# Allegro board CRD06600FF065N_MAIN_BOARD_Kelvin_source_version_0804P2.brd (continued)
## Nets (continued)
N165538091: RV1.1 RV2.2
N165801940: D1.1(A) R4.1

Pads without a net: CON2 2; J3 1 6 8 13; J4 5 9 12; J7 3 4 7 8; J8 3; NOREF#2 1; NOREF#7 1; NOREF#9 1; NOREF#14 1; NOREF#15 1; NOREF#16 1; T1 1 4 8 10 11; U5 7 12 13; U10 6 7 10 11; U35 1 4

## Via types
v1: diameter 0.61, hole 0.305, TOP to BOTTOM, 516 vias

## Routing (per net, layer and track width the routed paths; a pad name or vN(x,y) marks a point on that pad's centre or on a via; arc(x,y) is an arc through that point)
+5V_A: length 118
  TOP w0.508: R596.1 107.39,137.04 v1(107.6,136.83)
  TOP w0.635: C610.2 108.05,137.28 v1(107.6,136.83)
  ART05 w0.508: v1(85.34,140.34) 87.89,137.79 103.53,137.79 105.49,135.84 106.61,135.84 v1(107.6,136.83) 104.78,139.65 v1(104.78,142.24) 104.78,143.72 121.83,160.77 132.39,160.77 134.39,162.78 134.39,171.54 138.99,176.13 154.7,176.13 v1(156.21,174.62)
  BOTTOM w0.508: v1(107.6,136.83) 107.34,136.83 107.01,137.16 R242.2 ; v1(104.78,142.24) 104.65,142.12 C611.1 R246.1 ; R573.1 159.26,169.54 C596.2 157.6,170.06 156.21,171.45 v1(156.21,174.62)
-3V_PSW1: length 207.2
  ART05 w0.508: v1(205.74,71.75) 205.74,100.61 191.92,114.43 164.85,114.43 162.94,116.33 124.49,116.33 v1(119.28,121.54) 119.28,121.06 114.55,116.33 v1(99.95,116.33) 84.33,116.33 77.98,122.68 v1(76.58,122.68)
  BOTTOM w0.508: U106.8 v1(119.28,121.54) 119.28,122.49 C46.2 119.01,122.94 C614.2 ; v1(99.95,116.33) 99.95,111.9 ZD14.1 102.1,110.74 103,110.74 C45.2 ; C525.2 63.78,118.62 64.26,119.1 64.88,119.1 D47.1 65.16,117.94 66.76,116.34 C37.2 70.37,116.34 ZD13.1 75.74,117.09 76.2,117.55 U5.9 76.2,120.02 76.58,120.39 C38.2 76.58,121.29 v1(76.58,122.68)
-3V_PSW2: length 60.9
  ART03 w0.508: v1(162.2,121.54) 164.24,119.51 177.16,119.51 193.43,103.24 193.43,99.6 191.18,97.36 191.18,90.12 v1(192.41,88.9)
  BOTTOM w0.508: C499.2 C613.2 161.94,122.94 C41.2 162.2,122.49 v1(162.2,121.54) U104.8
-3V_PSW3: length 44.4
  ART05 w0.508: v1(87,117.47) 83.94,120.53 82.28,120.53 82.19,120.45 81.51,120.45 80.34,121.61 80.34,122.86 v1(80.13,123.07) 80.26,123.19 80.26,128.02 73.66,134.62 v1(63.5,134.62)
  BOTTOM w0.508: v1(80.13,123.07) C496.2 81.28,121.54 C33.2 81.02,120.31 81.52,119.82 82.16,119.82 82.55,119.42 U5.14 ; v1(87,117.47) C524.2 87.12,118.75 D48.1
-3V_PSW4: length 89.8
  ART03 w0.508: v1(124.97,41.66) 125.15,41.47 135.89,41.47 139.01,38.35 155.45,38.35 158.75,41.66 v1(165.82,41.66)
  ART05 w0.508: U21.5 170.31,24.13 170.81,24.64 170.81,36.66 v1(165.82,41.66)
  BOTTOM w0.508: C561.2 165.82,42.8 C563.2 165.95,41.78 v1(165.82,41.66) 171.41,41.66 173.37,43.62 U109.8 ; C547.2 124.93,42.8 C549.2 125.06,41.75 v1(124.97,41.66) 130.52,41.66 132.49,43.62 U107.8 ; U21.5 169.17,24.13
-3V_PSW5: length 42.4
  ART05 w0.508: U19.5 122.43,26.04 117.86,30.61 117.86,37.34 115.95,39.24 110.87,39.24 v1(108.2,41.91)
  BOTTOM w0.508: C542.2 107.82,41.91 v1(108.2,41.91) C537.2 109.09,42.93 109.47,42.55 112.52,42.55 113.92,43.94 U108.8
-3V_PSW7: length 29.7
  ART05 w0.508: v1(149.05,41.91) 147.45,40.31 147.45,34.8 151,31.24 151,28.01 U20.5
  BOTTOM w0.508: U110.8 154.76,43.94 153.37,42.55 150.62,42.55 150.24,42.93 C552.2 v1(149.05,41.91) 148.67,41.91 C556.2
-3V_PSW9: length 97.7
  ART02 w0.508: U22.5 82.74,16.13 55.45,16.13 52.44,19.14 25.8,19.14 20.96,23.98 20.96,40.13 v1(22.86,42.04)
  BOTTOM w0.508: C570.2 22.61,42.04 v1(22.86,42.04) C566.2 23.87,42.93 24.26,42.55 27.18,42.55 28.57,43.94 U112.8
-3V_PSW10: length 121.1
  ART05 w0.508: U24.5 112.56,16.23 112.56,20.01 110.78,21.8 108.02,21.8 99.95,29.87 99.95,36.58 94.49,42.04 v1(83.07,42.04) 80.15,44.96 77.47,44.96 72.77,40.26 64.39,40.26 63.12,38.99 57.02,38.99 53.98,42.04 v1(42.16,42.04)
  BOTTOM w0.508: v1(83.07,42.04) 88.65,42.04 90.62,44 U113.8 ; v1(83.07,42.04) 82.43,42.04 C589.2 ; v1(83.07,42.04) 83.19,42.16 C591.2 ; C575.2 41.53,42.04 v1(42.16,42.04) ; v1(42.16,42.04) 47.75,42.04 49.72,44 U111.8 ; v1(42.16,42.04) 42.29,42.16 C577.2
-3V_PSW11: length 88.7
  ART02 w0.508: U23.5 96.22,14.71 96.22,20.24 95.12,21.34 95.12,49.91 91.02,54.02 74.71,54.02 73.74,53.05 73.74,47.58 68.71,42.55 64.26,42.55 v1(63.75,42.04)
  BOTTOM w0.508: U114.8 69.47,43.94 68.07,42.55 65.15,42.55 64.77,42.93 C580.2 v1(63.75,42.04) 63.5,42.04 C584.2
AGND: length 572.5
  TOP w0.381: U10.8 v1(101.35,38.1)
  TOP w0.508: C101.2 107.68,27.82 107.65,27.85 C102.1 v1(105.96,26.86)
  ART02 w0.508: J5.6 218.43,42.55 ; J5.8 218.43,40.01 ; 159.45,7.62 J7.9 161.35,9.51 ; J3.3 218.43,71.75 ; J3.21 218.43,94.61 ; 166.43,3.19 J7.6 ; 212.1,71.75 214,71.75 ; 212.1,69.22 214,69.22 214,67.32
  ART02 w1.016: 205.23,16.36 C594.2 ; C594.2 208.79,16.36 ; C594.2 207.01,18.13 ; C594.2 207.01,14.58 ; U20.2 150.29,17.78 ; U20.2 148.39,19.67 ; U20.2 146.5,17.78 ; U21.2 169.48,18.4 ; U21.2 167.58,16.51 ; U21.2 171.37,16.51 ; U19.2 132,18.41 ; U19.2 128.21,18.41 ; U19.2 130.11,20.31
  ART03 w1.016: U15.2 201.73,65.27 ; U15.2 200.6,64.14 ; U15.2 202.87,64.14 ; U17.2 201.73,86.22 ; U17.2 200.6,85.09 ; U17.2 202.87,85.09 ; J3.21 217.67,94.61
  GND04 w0.508: 166.43,3.19 J7.6 ; J7.9 161.35,9.51
  GND04 w1.016: U19.2 132,18.41 ; U19.2 130.11,20.31 ; U19.2 128.21,18.41 ; 205.23,16.36 C594.2 207.01,18.13 ; 148.39,18.41 148.39,20.31 ; 148.39,18.41 150.29,18.41 ; 148.39,18.41 146.5,18.41 ; U21.2 169.48,18.4 ; U21.2 167.58,16.51 ; U21.2 171.37,16.51
  ART05 w0.254: 216.79,40.01 218.97,37.82 218.97,31.55 v1(217.34,29.92)
  ART05 w0.508: 214,69.22 J3.3 ; v1(218.43,51.29) 218.67,51.04 218.67,41.03 217.64,40.01 J5.8 ; v1(211.89,38.94) 210.82,37.87 v1(210.82,33.02) 209.65,31.85 209.65,29.71 200.21,20.26 v1(189.87,20.26) 181.67,20.26 v1(181.61,20.32) 177.42,16.13 v1(175.9,16.13) 169.86,16.13 U21.2 166.03,16.51 164.01,14.49 151.69,14.49 U20.2 147.32,17.78 144.03,14.49 128.18,14.49 125.47,17.2 125.47,19.41 111.51,33.37 111.51,33.85 111.02,34.34 v1(109.62,34.34) 108.21,34.34 106.54,32.66 106.54,27.45 v1(105.96,26.86) 109.27,26.86 113.95,22.18 113.95,18.7 122.48,10.17 200.83,10.17 C594.2 207.01,19.68 v1(207.65,20.32) 214.25,26.92 215.73,26.92 217.34,28.54 v1(217.34,29.92) ; 199.38,70.5 205.86,70.5 207.89,72.53 207.89,76.83 v1(212.09,81.03) ; U15.2 201.73,65.27 ; U15.2 202.87,64.14 ; U15.2 200.6,64.14
  ART05 w1.016: U18.2 59.69,143.69 ; U18.2 59.69,139.91 ; U18.2 61.58,141.8
  BOTTOM w0.381: C40.2 75.56,108.46 C598.2 ; C540.2 C541.2 v1(125.86,33.66) ; U103.5 v1(177.16,174.62) ; 115.57,109.48 115.57,109.47 ; C605.2 v1(113.92,32.64)
  BOTTOM w0.508: 159.66,115.44 159.92,115.7 163.95,115.7 C530.2 164.98,115.06 165.99,114.05 C531.2 166.75,113.66 167,113.41 C601.2 ; 159.66,115.44 159.66,115.73 158.88,115.73 158.39,115.24 U104.4 158.39,113.45 v1(157.66,112.72) 158.5,111.88 C43.2 ; 159.66,115.44 U104.3 ; R550.2 C544.2 v1(109.62,34.34) ; v1(189.17,47.55) 189.17,46.39 C604.1 ; C533.2 C532.2 v1(116.52,37.6) ; U106.3 116.74,115.7 ; 116.74,115.7 121.41,115.7 C48.2 122.81,115.06 123.32,114.55 C47.2 124.85,113.66 C602.2 ; 116.74,115.7 116.74,115.73 115.96,115.73 115.47,115.24 U106.4 115.47,113.45 v1(114.74,112.72) 115.57,111.88 C44.2 R73.2 ; C595.1 v1(174.62,177.16) ; R70.2 v1(78.11,107.31) ; C555.2 C554.2 174.91,36.14 v1(177.2,36.14) 177.2,35.96 177.98,35.18 C608.2 ; C88.2 v1(192.91,24.77) ; 123.19,139.7 121.92,138.43 C612.2 ; 123.19,139.7 120.02,142.88 U35.5 ; 123.19,139.7 124.46,139.7 125.96,138.2 134.72,138.2 137.41,140.89 137.41,143.89 138.96,145.44 142.29,145.44 144.76,147.91 144.76,152.23 145.36,152.83 145.36,155.9 144.93,156.33 C1.2 v1(144.15,164.47) ; v1(80.84,111.12) 81.28,111.57 U5.4 ; v1(204.4,43.33) 205.36,43.33 U9.3 ; R73.2 v1(114.68,110.49) ; R73.2 115.57,109.48 ; U4.4 v1(198.75,39.37) ; v1(158.5,109.48) R72.2 ; C27.1 180.09,170.81 180.72,171.45 v1(180.97,171.45) ; U107.3 v1(129.95,38.1) ; R554.2 v1(150.04,34.67) ; C607.2 v1(159.13,38.35) ; v1(121.82,33.66) C543.2 R548.2 ; U110.3 v1(152.22,40.51) ; U109.3 v1(170.83,40.51) ; C40.2 v1(75.56,107.31) ; C39.2 v1(76.83,107.31) ; v1(201.93,43.81) 202.05,43.94 R136.1 ; v1(195.07,46.15) 195.07,45.15 C84.1 ; C606.2 v1(126.35,31.12) ; R552.2 C557.2 v1(168.3,34.2) ; U107.4 v1(128.68,38.08) ; v1(157.73,38.73) C551.2 C550.2 ; C26.1 v1(181.71,177.16) ; C93.2 v1(201.67,39.25) ; U108.3 v1(111.38,38.17) ; U55.3 201.93,172.6 v1(200.66,171.33) R539.1 ; v1(182.37,27.69) 182.37,27.69 C603.1 ; C558.2 v1(151.55,34.67) ; C248.1 v1(190.14,29.72) ; U110.4 v1(150.95,40.51) ; R68.2 v1(80.64,107.31) ; U2.4 v1(193.55,172.72) 193.8,172.46 C592.2 196.08,171.33 C478.2 ; C597.1 v1(177.16,168.28) ; C35.2 v1(85.72,107.31) ; C36.2 v1(81.92,107.31) ; R69.2 v1(79.38,107.31) ; U109.4 v1(169.56,40.51) ; U108.4 v1(110.11,38.16) ; R67.2 v1(87,107.31)
  vias: v1(97.28,109.86) v1(115.95,104.78) v1(123.43,100.24) v1(130.18,100.24) v1(130.94,166.75) v1(130.94,165.61) v1(164.96,109.59) v1(167.78,109.36) v1(171.99,108.19) v1(180.21,99.95) v1(180.21,89.66) v1(182.88,16.89) v1(184.15,16.89) v1(185.42,16.89) v1(186.12,20.23) v1(186.69,16.89) v1(187.96,16.89) v1(189.23,16.89) v1(189.23,15.37) v1(190.5,15.37) v1(190.58,16.74) v1(191.85,16.74) v1(191.9,15.37) v1(193.12,16.74) v1(193.17,15.37) v1(194.39,16.74) v1(194.44,15.37) v1(194.82,86.49) v1(194.82,85.09) v1(195.58,66.1) v1(195.66,16.74) v1(195.71,15.37) v1(196.22,86.49) v1(197.1,16.76) v1(197.1,15.37) v1(197.61,86.49) v1(197.61,85.09) v1(198.12,17.72) v1(198.37,16.76) v1(199.64,16.76) v1(200.91,16.76) v1(201.93,18.36) v1(202.44,16.76) v1(203.2,65.41) v1(204.47,65.41) v1(212.58,51.29)
AGND_N: length 153.7
  TOP w0.508: C610.1 108.08,135.77 107.57,135.26 v1(107.57,135.25) ; C278.1 R243.2 v1(93.34,134.62) ; U34.4 v1(97.28,134.62) ; C281.2 v1(93.34,139.7)
  ART03 w1.016: 82.62,128.63 Q4.3 ; Q4.3 85.16,126.09 ; Q4.3 85.16,131.17 ; 69.85,139.91 U18.6 69.85,143.69 ; 35.77,126.5 D2.3 ; D2.3 38.15,128.89 ; D2.3 35.77,131.28
  GND04 w0.508: v1(163.19,174.62) 161.93,173.35 159.38,173.35 v1(158.12,174.62)
  ART05 w0.508: v1(158.12,174.62) 155.58,177.16 138.21,177.16 133.61,172.56 133.61,163.31 131.99,161.69 120.78,161.69 98.79,139.7 v1(93.34,139.7)
  BOTTOM w0.381: U103.4 v1(163.19,174.62) 163.19,173.74 163.58,173.35 U103.3
  BOTTOM w0.508: C496.1 C497.2 82.55,125.73 ; v1(101.6,136.81) 101.6,136.81 Q60.3 ; v1(158.12,174.62) 158.75,173.99 C596.1 159.38,171.57 159.89,172.09 C30.2 C29.1 ; v1(93.34,139.7) 88.87,139.7 88.27,139.09 88.27,136.4 ; C611.2 106.17,142.27 105.22,143.22 104.49,143.22 103.5,142.24 v1(103.5,140.97) C282.1 ; v1(107.57,135.25) 106.93,134.62 C280.2 R241.1 ; C524.1 87,121.16 C599.1 ; v1(107.57,138.43) C279.2
  vias: v1(80.9,138.94) v1(80.9,136.91) v1(83.19,134.62) v1(83.18,133.63) v1(84.44,133.65) v1(84.45,134.62) v1(85.34,136.78) v1(85.72,134.62) v1(85.74,133.65) v1(87,134.62) v1(87,133.69) v1(88.27,134.62) v1(88.33,133.74) v1(89.53,134.62) v1(89.56,133.73) v1(89.79,136.78) v1(90.81,134.62) v1(92.08,134.62) v1(92.18,133.7) v1(93.33,133.75) v1(97.27,133.79)
PGND: length 487.6
  TOP w1.016: C11.2 175.74,165.8 ; C11.2 173.1,163.16 ; C11.2 173.1,168.45 ; C11.2 170.46,165.8 ; 212.2,142.03 C14.2 ; C14.2 214.84,144.67 ; C14.2 212.2,147.31 ; C14.2 209.56,144.67 ; CB6.2 208.84,46.35 ; CB6.2 204.06,46.35 ; CB6.2 206.45,43.97 ; C15.2 194.16,165.8 ; C15.2 188.87,165.8 ; C15.2 191.52,163.16 ; C15.2 191.52,168.45 ; C13.2 214.84,107.84 ; C13.2 212.2,110.48 ; C13.2 209.56,107.84 ; C16.2 212.2,165.73 ; C16.2 212.2,160.44 ; C16.2 209.56,163.08 ; C16.2 214.84,163.08 ; 152.3,147.26 C12.2 ; C12.2 157.58,147.26 ; C12.2 154.94,149.9 ; 212.2,123.61 C17.2 ; C17.2 209.56,126.25 ; C17.2 212.2,128.9 ; C17.2 214.84,126.25 ; 204.92,36.04 CB7.2 207.31,33.66 ; 188.87,147.39 C18.2 ; C18.2 194.16,147.39 ; C18.2 191.52,150.03 ; 154.53,163.28 C10.2 ; C10.2 151.89,165.93 ; C10.2 154.53,168.57 ; C10.2 157.17,165.93 ; C9.2 176,147.26 ; C9.2 173.35,149.9 ; C9.2 170.71,147.26
  GND04 w0.508: v1(181.61,40.64) 186.69,35.56 v1(186.69,34.92) 186.69,29.21 v1(184.78,27.3)
  GND04 w1.016: C10.2 151.47,165.93 ; C10.2 154.53,162.75 ; C10.2 154.53,169.08 ; C10.2 157.91,165.93 ; C11.2 169.33,165.8 ; C11.2 173.1,168.86 ; C11.2 176.44,165.8 ; C11.2 173.1,162.46 ; C17.2 212.2,122.72 ; C17.2 208.74,126.25 ; C17.2 215.82,126.25 ; C17.2 212.2,129.48 ; C16.2 208.94,163.08 ; C16.2 215.59,163.08 ; C16.2 212.2,159.72 ; C16.2 212.2,166.3 ; C9.2 173.35,144.29 ; C9.2 170.57,147.26 ; C9.2 173.35,150.15 ; C9.2 176.23,147.26 ; C13.2 208.95,107.84 ; C13.2 212.2,104.13 ; C13.2 212.2,111.33 ; C13.2 216.07,107.84 ; 25.88,128.89 D2.4 ; D2.4 28.27,131.28 ; D2.4 30.65,128.89 ; D2.4 28.27,126.5 ; C18.2 194.39,147.39 ; C18.2 191.52,150.32 ; C18.2 191.52,144.35 ; C18.2 188.49,147.39 ; CB7.2 204.92,36.31 ; CB7.2 202.2,33.66 ; CB7.2 207.75,33.66 ; C12.2 158.05,147.26 ; C12.2 154.94,150.16 ; C12.2 154.94,144.04 ; C12.2 152,147.26 ; 204.06,46.35 CB6.2 ; CB6.2 206.45,43.97 ; CB6.2 208.84,46.35 ; CB6.2 206.45,48.74 ; C15.2 188.22,165.8 ; C15.2 191.52,162.43 ; C15.2 191.52,168.93 ; C15.2 195.11,165.8 ; C14.2 215.72,144.67 ; C14.2 212.2,147.87 ; C14.2 208.91,144.67 ; C14.2 212.2,141.3
  ART05 w1.016: C14.2 212.2,141.53 ; C14.2 209.03,144.67 ; C14.2 212.2,147.39 ; C18.2 194.17,147.39 ; C18.2 191.52,150.04 ; C18.2 191.52,144.42 ; C17.2 212.2,122.94 ; C17.2 208.97,126.25 ; C17.2 212.2,129.47 ; 212.2,110.66 C13.2 208.95,107.84 ; C12.2 154.94,150.54 ; C12.2 154.94,144.29 ; C12.2 158.16,147.26 ; C9.2 173.35,150.24 ; C9.2 176.59,147.26 ; C9.2 173.35,144.34 ; C11.2 176.39,165.8 ; C11.2 170.08,165.8 ; C11.2 173.1,162.57 ; 157.76,165.93 C10.2 154.53,162.61 ; C15.2 188.3,165.8 ; C15.2 194.95,165.8 ; C15.2 191.52,162.48 ; 209.09,163.08 C16.2 212.2,159.61
  BOTTOM w0.508: C34.2 68.58,106.68 69.22,106.05 v1(69.85,106.05) ; R66.2 70.87,106.3 v1(71.12,106.05) ; v1(69.85,112.01) 70.36,112.52 70.86,112.52 ZD13.2 ; v1(68.45,112.01) 68.58,112.14 C37.1 ; C96.2 183.09,41.91 182.73,41.55 182.73,40.67 R135.2 v1(181.61,40.64) 180.28,41.97 180.28,53.4 179.9,53.78 C81.1 179.9,55.85 179.55,56.2 179.55,61.29 180.73,62.48 182.24,62.48 ; v1(186.69,34.92) C89.2 C90.2 ; C87.1 R123.2 v1(184.78,27.3) 184.78,27.05 183.95,26.22 183.95,25.5 184.69,24.77 C82.1 185.93,23.52 186.95,22.5 201.7,22.5 203.32,24.13 R129.1 C92.2 205.05,26.67 206.45,28.07 206.45,30.53 205.48,31.5 203.54,31.5 203.27,31.23 203.27,30.53 C99.1
  BOTTOM w1.016: 212.2,161 C16.2 210.1,163.08 ; C15.2 191.52,163.81 ; C15.2 189.56,165.8 ; C15.2 193.65,165.8 ; C9.2 171.14,147.26 ; C9.2 173.35,149.4 ; C9.2 175.57,147.26 ; C10.2 152.25,165.93 ; C10.2 154.53,163.82 ; C10.2 154.53,167.76 ; C10.2 156.53,165.93 ; 189.29,147.39 C18.2 191.52,149.93 ; C11.2 173.1,163.66 ; C11.2 171.02,165.8 ; C11.2 175.02,165.8 ; C12.2 157.05,147.26 ; C12.2 154.94,149.48 ; C12.2 152.6,147.26
  vias: v1(184.15,70.48) v1(184.15,69.22) v1(184.15,67.94) v1(184.15,66.67) v1(184.15,65.41) v1(184.15,64.14) v1(184.15,62.87) v1(184.15,61.59) v1(184.15,60.33) v1(184.15,59.05) v1(184.15,57.78) v1(184.15,56.52) v1(184.78,99.69) v1(184.78,98.42) v1(184.78,97.16) v1(184.78,95.89) v1(184.78,94.61) v1(184.78,93.34) v1(184.78,92.08) v1(184.78,90.81) v1(184.78,89.53) v1(185.42,70.48) v1(185.42,69.22) v1(185.42,67.94) v1(185.42,66.67) v1(185.42,65.41) v1(185.42,64.14) v1(185.42,62.87) v1(185.42,61.59) v1(185.42,60.33) v1(185.42,59.05) v1(185.42,57.78) v1(185.42,56.52) v1(186.06,99.69) v1(186.06,98.42) v1(186.06,97.16) v1(186.06,95.89) v1(186.06,94.61) v1(186.06,93.34) v1(186.06,92.08) v1(186.06,90.81) v1(186.06,89.53) v1(204.47,159.39) v1(204.47,158.12) v1(204.47,156.84) v1(204.47,155.57) v1(204.47,154.31) v1(205.74,159.39) v1(205.74,158.12) v1(205.74,156.84) v1(205.74,155.57) v1(205.74,154.31) v1(207.01,159.38) v1(207.01,158.12) v1(207.01,156.84) v1(207.01,155.57) v1(207.01,154.31)
SGND: length 80.2
  TOP w0.508: C103.1 v1(88.78,26.03) ; C100.2 v1(85.72,27.05) ; U10.9 v1(91.44,38.1)
  GND04 w0.508: U24.2 110.79,5.71 ; U24.2 109.66,6.85 ; U24.2 108.53,5.71 ; U24.2 109.66,4.58 ; 214,20.95 215.13,20.95 ; 214,20.95 214,19.82 ; 214,20.95 212.86,20.95 ; 216.53,12.2 216.53,13.34 ; 216.53,13.34 216.53,14.47 ; 216.53,13.34 217.67,13.34 ; 216.53,13.34 215.4,13.34 ; 85.53,4.58 U22.2 ; U22.2 86.66,5.71 ; U22.2 85.53,6.85 ; U22.2 84.4,5.71 ; 96.46,5.71 U23.2 ; U23.2 97.59,4.58 ; U23.2 97.59,6.85 ; U23.2 98.73,5.71 ; 214,15.88 215.13,15.88 ; 214,15.88 212.86,15.88 ; 214,15.88 214,17.01 ; 214,15.88 214,14.74 ; 133.81,6.49 J8.5 ; J8.5 132.68,7.62 ; J8.5 133.81,8.75 ; J8.5 134.94,7.62
  ART05 w0.508: U24.2 110.79,5.71 ; U24.2 109.66,4.58 ; U24.2 108.53,5.71 ; U24.2 109.66,6.85 ; U23.2 98.73,5.71 ; U23.2 97.59,4.58 ; U23.2 96.46,5.71 ; U23.2 97.59,6.85 ; 85.53,4.58 U22.2 ; U22.2 86.66,5.71 ; U22.2 84.4,5.71 ; U22.2 85.53,6.85 ; 132.68,7.62 J8.5 ; J8.5 133.81,6.49 ; J8.5 134.94,7.62
  BOTTOM w0.508: R560.2 v1(87.42,34.53) ; v1(24.28,34.34) C572.2 R558.2 ; v1(31.18,37.6) C564.2 C565.2 ; C582.2 v1(94.38,37.03) ; C571.2 v1(45.03,34.52) ; C569.2 v1(52.43,35.76) ; U112.3 v1(26.03,38.17) ; C579.2 C578.2 v1(72.07,37.6) ; C585.2 v1(85.93,34.52) ; C583.2 v1(94.35,35.76) ; C568.2 v1(52.47,37.03) ; U113.3 v1(88.08,38.1) ; R556.2 v1(46.52,34.53) ; U112.4 v1(24.76,38.16) ; U111.3 v1(47.18,38.1) ; R563.2 C586.2 v1(65.17,34.34) ; U111.4 v1(45.91,38.08) ; U114.4 v1(65.66,38.16) ; U114.3 v1(66.93,38.17) ; U113.4 v1(86.81,38.08)
  vias: v1(86.87,7.24) v1(88.14,7.24) v1(89.41,7.24) v1(90.68,7.24) v1(98.93,7.24) v1(100.2,7.24) v1(101.47,7.24) v1(102.74,7.24) v1(111,7.24) v1(112.27,7.24) v1(113.54,7.24) v1(114.81,7.24) v1(122.68,3.05) v1(122.68,2.16)
_PFCREF1.6V: length 14.8
  BOTTOM w0.508: C28.1 R537.2 186.85,171.33 190.79,175.26 U2.2 193.34,175.26 193.68,175.6 193.68,176.08 193.22,176.53 U2.1
_PREF1.6V: length 13.1
  ART03 w0.508: v1(195.94,41.91) 190.35,36.33 v1(190.35,36.06)
  BOTTOM w0.508: U4.2 v1(195.94,41.91) 195.88,41.96 195.88,42.98 196.09,43.18 U4.1 ; R119.1 189.24,36.06 v1(190.35,36.06)
AC_L: length 91.9
  ART02 w1.016: D2.2 43.27,131.28 ; D2.2 43.27,126.5 ; D2.2 45.65,128.89 ; 120.6,156.16 RLY1.3 ; RLY1.3 124.25,159.8 ; RLY1.3 127.89,156.16 ; RLY1.3 124.25,152.51 ; 132.92,141.64 RV2.1 130.5,144.06 ; XC4.1 122.63,148.39 ; XC4.1 120.25,146.01 ; XC4.1 125.02,146.01
  ART03 w1.016: RV2.1 127.84,141.64 ; RV2.1 133.31,141.64 ; RV2.1 130.5,138.94 ; RV2.1 130.5,144.31 ; 124.25,152.04 RLY1.3 120.31,156.16 ; XC4.1 122.63,143.38 ; XC4.1 125.28,146.01 ; XC4.1 120.12,146.01 ; XC4.1 122.63,148.63
  GND04 w1.016: 120.25,146.01 XC4.1 ; XC4.1 125.02,146.01 ; XC4.1 122.63,148.39 ; XC4.1 122.63,143.62 ; RV2.1 130.5,144.06 ; RV2.1 128.09,141.64 ; RV2.1 132.92,141.64 ; 124.25,152.51 RLY1.3 120.6,156.16 ; 45.65,128.89 D2.2 43.27,131.28
AC_L_SAMP: length 6.1
  BOTTOM w0.508: R14.1 125.37,174.62 124.7,173.96 RLY1.4
AC_L_SAMP_D: length 177.5
  ART05 w0.508: v1(142.24,173.99) 143.73,172.5 168.46,172.5 174.02,178.05 209.04,178.05 218.74,168.35 218.74,82.22 217.17,80.64 215.82,80.64 214.55,79.38 214,79.38
  BOTTOM w0.508: R16.2 141.6,174.62 v1(142.24,173.99)
AC_N_D: length 210
  ART05 w0.508: v1(115.57,149.86) 123.69,149.86 135.24,161.41 135.24,164.37 142.61,171.74 170.4,171.74 175.75,177.09 180.58,177.09 181.44,176.24 186.6,176.24 187.43,177.06 208.38,177.06 217.81,167.64 217.81,83.92 217.07,83.19 215.24,83.19 214,81.94 214,81.92
  BOTTOM w0.508: R22.2 v1(115.57,149.86)
AD_DC_CUR: length 60.8
  ART03 w0.508: v1(189.87,41.91) 190.21,41.91 191.91,43.6 191.91,43.62 192.89,44.6 192.89,45.76 208.5,61.36 208.43,61.43 208.43,82.55 212.88,87 214,87
  BOTTOM w0.508: C94.2 190.57,44.52 189.77,43.72 R132.2 189.77,42.01 v1(189.87,41.91) U4.7
CAN5V_GND: length 79.4
  ART03 w0.508: J8.2 146.4,2.65 176.47,2.65 178.83,5.01 178.83,7.41 182.01,10.6 213.8,10.6 214,10.79
CAN_5V: length 78.2
  ART03 w0.508: 214,13.34 212.6,14.73 205.23,14.73 202.24,11.74 181.72,11.74 177.94,7.97 177.94,5.8 175.68,3.53 148.06,3.53 J8.1
CLAMPA: length 35.8
  ART05 w0.762: v1(146.94,117.35) 150.62,117.35 153.8,120.52 159.94,120.52 v1(160.93,121.51) 161.8,120.65 169.42,120.65 v1(171.7,118.36)
  BOTTOM w0.508: U104.7 v1(160.93,121.51)
  BOTTOM w0.762: v1(146.94,117.35) 147.07,117.22 R216.2 148.46,117.48 R602.1 ; R217.2 171.7,117.47 v1(171.7,118.36) R604.1
CLAMPB: length 36.6
  ART05 w0.762: v1(128.78,118.36) 126.11,118.36 122.05,122.43 118.87,122.43 118.01,121.56 v1(118.01,121.51) 117.7,121.51 113.54,117.35 v1(104.01,117.35)
  BOTTOM w0.508: U106.7 v1(118.01,121.51)
  BOTTOM w0.762: R605.1 105.54,117.48 R219.2 104.14,117.22 v1(104.01,117.35) ; R218.2 128.78,117.47 v1(128.78,118.36) R603.1
CLAMPQ8: length 7.6
  BOTTOM w0.762: R78.1 27.82,50.04 Q8.4 27.3,49.48 U112.7
CLAMPQ9: length 7.6
  BOTTOM w0.762: R79.2 68.7,50.04 Q9.4 68.17,45.02 U114.7
CLAMPQ10: length 9.7
  BOTTOM w0.762: U108.7 112.64,45 Q10.4 114.4,49.53 114.44,49.57 114.47,49.57 114.94,50.04 R80.1 115.44,50.04 R564.1
CLAMPQ11: length 9.9
  BOTTOM w0.762: U110.7 153.48,45 Q11.4 153.99,50.04 R81.2 156.21,50.12 R565.2
CLAMPQ12: length 7.6
  BOTTOM w0.762: U111.7 48.45,49.49 Q12.4 49,50.04 R94.1
CLAMPQ13: length 7.6
  BOTTOM w0.762: R95.2 89.9,50.04 Q13.4 89.35,49.49 U113.7
CLAMPQ14: length 10.8
  BOTTOM w0.762: U107.7 131.22,45.87 131.74,46.39 132.75,46.39 133.78,47.42 Q14.4 134.31,50.04 R97.1 R566.1
CLAMPQ15: length 4.1
  BOTTOM w0.762: 174.67,47.79 173.23,46.35 172.73,46.35 172.1,45.73 U109.7
DCOCP: length 72.5
  ART03 w0.508: 214,89.53 215.26,88.27 217.27,88.27 217.86,87.68 217.86,65 196.8,43.94 196.8,33.61 v1(194.31,31.11)
  BOTTOM w0.508: D8.3 v1(194.31,31.11)
DCPWM1A_1H: length 139.8
  ART05 w0.381: v1(110.62,33.15) 110.62,32.55 123.64,19.53 123.64,17.1 127.02,13.72 165.17,13.72 166.72,15.28 177.71,15.28 181.77,19.34 200.5,19.34 210.47,29.31 210.47,31.42 211.74,32.7 211.74,37.1 213.41,38.77 214.63,38.77 215.25,39.39 215.25,40.41 216.13,41.28 216.96,41.28 217.73,42.05 217.73,43.89 J5.4
  BOTTOM w0.508: v1(110.62,33.15) 111.08,33.15 v1(112.19,34.26) 112.19,35.39 R551.1
DCPWM1A_1L: length 124.9
  ART03 w0.381: v1(163.7,21.15) 163.63,21.08 v1(160.66,21.08)
  ART05 w0.381: v1(163.7,21.15) 179,21.15 180.16,22.32 199.55,22.32 207.96,30.73 207.96,38.28 210.96,41.28 214.62,41.28 215.26,41.93 215.26,46.35 J5.2 ; v1(124.33,33.68) 124.33,33.66 125.35,32.64 128.52,32.64 131.7,35.81 139.83,35.81 140.72,34.92 140.72,24.89 144.53,21.08 v1(160.66,21.08)
  BOTTOM w0.381: v1(124.33,33.68) 124.36,33.71 R549.1
DCPWM2A_2H: length 89.9
  ART05 w0.381: 214,40.01 211.46,40.01 208.88,37.43 208.88,30.27 199.97,21.36 180.28,21.36 179.18,20.25 163.39,20.25 159.64,24 159.64,32.77 158.5,33.91 149.73,33.91 148.97,34.67 v1(148.54,34.67)
  BOTTOM w0.381: R555.1 v1(148.54,34.67)
DCPWM2A_2L: length 63.1
  ART05 w0.381: v1(171.87,33.15) 172.34,32.68 172.34,26.92 175.98,23.29 199.18,23.29 206.96,31.08 206.96,38.75 210.76,42.55 214,42.55
  BOTTOM w0.381: R553.1 v1(171.87,33.15)
DRV_L_G: length 74.9
  ART03 w0.508: v1(161.5,44.2) 160.02,44.2 155.07,39.24 139.83,39.24 136.4,42.67 132.59,42.67 131.06,44.2 v1(120.61,44.2)
  ART05 w0.508: v1(161.5,44.2) 161.5,42.59 163.96,40.13 163.96,38.48 167.51,34.92 167.51,28.83 169.48,26.87 U21.6
  BOTTOM w0.508: R542.2 164.81,44.7 C561.1 164.3,44.2 C559.2 v1(161.5,44.2) ; R541.1 123.92,44.7 C547.1 123.41,44.2 C545.2 v1(120.61,44.2)
DRVA: length 10.9
  ART05 w0.762: v1(116.46,45.72) 113.66,45.72 v1(111.38,43.43)
  BOTTOM w0.762: R80.2 115.44,46.74 v1(116.46,45.72) 116.59,45.86 D57.2 ; U108.6 v1(111.38,43.43)
DRVA_G: length 49.6
  ART05 w0.508: U19.6 130.81,28.57 131.7,29.46 131.7,31.5 130.68,32.51 129.67,32.51 126.75,29.59 123.19,29.59 120.4,32.38 120.4,38.61 117.86,41.15 111.38,41.15 108.08,44.45 v1(105.79,44.45)
  BOTTOM w0.508: v1(105.79,44.45) C536.2 C537.1 108.2,44.96 110.1,46.85 Q10.3
DRVB: length 11.9
  ART05 w0.762: v1(135.51,45.59) 132.17,45.59 v1(129.89,43.31)
  BOTTOM w0.762: v1(129.89,43.31) 129.89,43.69 129.95,43.75 U107.6 ; D59.2 134.5,44.59 v1(135.51,45.59) 136.11,46.19 R97.2
DRVC: length 11
  ART05 w0.762: v1(157.3,45.72) 154.51,45.72 v1(152.22,43.43)
  BOTTOM w0.762: R81.1 156.29,46.74 v1(157.3,45.72) 157.57,45.98 D58.2 ; U110.6 v1(152.22,43.43)
DRVC_G: length 27.2
  ART05 w0.508: U20.6 149.86,29.41 149.86,30.99 146.05,34.8 146.05,43.86 v1(146.63,44.45)
  BOTTOM w0.508: Q11.3 150.94,46.93 149.05,45.03 C552.1 C553.2 v1(146.63,44.45)
DRVD: length 10.9
  ART05 w0.762: v1(175.27,40.26) 173.82,40.26 v1(170.77,43.31)
  BOTTOM w0.762: R98.1 175.27,41.96 v1(175.27,40.26) D60.2 ; U109.6 170.83,43.75 170.77,43.69 v1(170.77,43.31)
DRVSA: length 7.9
  ART05 w0.762: v1(26.03,43.43) 28.57,45.97 v1(30.1,45.97)
  BOTTOM w0.508: U112.6 v1(26.03,43.43)
  BOTTOM w0.762: R78.2 v1(30.1,45.97)
DRVSB: length 8.5
  ART05 w0.762: v1(47.12,43.31) 47.12,43.69 49.4,45.97 v1(51.31,45.97)
  BOTTOM w0.762: v1(47.12,43.31) 47.12,43.69 47.18,43.75 U111.6 ; R94.2 v1(51.31,45.97)
DRVSC: length 7.9
  ART05 w0.762: v1(70.99,45.97) 69.47,45.97 v1(66.93,43.43)
  BOTTOM w0.762: U114.6 v1(66.93,43.43) ; R79.1 v1(70.99,45.97)
DRVSD: length 8.3
  ART05 w0.762: v1(88.02,43.31) 90.69,45.97 v1(92.21,45.97)
  BOTTOM w0.762: v1(88.02,43.31) 88.02,43.69 88.08,43.75 U113.6 ; R95.1 v1(92.21,45.97)
EARTH:
  vias: v1(17.14,158.75) v1(17.14,157.48) v1(17.14,156.21) v1(17.14,154.94) v1(59.18,162.56) v1(59.18,161.29) v1(60.33,162.56) v1(60.33,161.29)
HM1: length 8.8
  GND04 w1.016: 85.31,83.09 T1.9 89.21,87.98
IPFC: length 103
  TOP w0.508: R244.2 v1(93.32,140.97)
  ART05 w0.508: v1(160.53,174.62) 157,178.15 137.58,178.15 132.78,173.36 132.78,163.78 131.65,162.64 120.1,162.64 98.42,140.97 v1(93.32,140.97)
  BOTTOM w0.508: R20.1 100.83,148.46 100.13,147.76 XC4.2 ; v1(160.53,174.62) R62.2 ; v1(93.32,140.97) 88.93,140.97 88.27,141.63 88.27,143
  vias: v1(88.27,149.86) v1(88.27,148.59) v1(88.27,147.32) v1(88.27,146.05) v1(88.27,144.78) v1(89.53,149.86) v1(89.53,148.59) v1(89.53,147.32) v1(89.53,146.05) v1(89.53,144.78) v1(90.81,149.86) v1(90.81,148.59) v1(90.81,147.32) v1(90.81,146.05) v1(90.81,144.78) v1(92.08,149.86) v1(92.08,148.59) v1(92.08,147.32) v1(92.08,146.05) v1(92.08,144.78) v1(93.34,147.32) v1(93.34,146.05) v1(93.34,144.78) v1(94.61,147.32) v1(94.61,146.05) v1(94.61,144.78) v1(95.89,147.32) v1(95.89,146.05) v1(95.89,144.78) v1(97.16,147.32) v1(97.16,146.05) v1(97.16,144.78)
IPFCSAMPLE: length 119
  BOTTOM w0.508: R65.1 C31.2 184.93,175.77 185.43,175.26 U2.7 187.85,175.26 190.15,177.56 206.7,177.56 218.8,165.46 218.8,91.8 J3.17
PCS+: length 66.8
  GND04 w0.508: v1(204.29,29.51) 202.69,27.91 189.38,27.91 187.5,26.04 v1(184.78,26.04) 183.82,27 183.82,31.06 185.17,32.4 185.17,35.81 v1(181.61,39.37)
  BOTTOM w0.508: v1(184.78,26.04) R117.2 ; v1(204.29,29.51) 203.99,29.21 R138.2 ; 175.9,62.54 177.47,62.54 178.68,61.33 178.68,56.24 178.38,55.94 C81.2 178.38,53.69 179.31,52.76 179.31,41.67 v1(181.61,39.37) R120.2
  vias: v1(168.91,71.12) v1(168.91,69.85) v1(168.91,68.58) v1(170.18,71.12) v1(170.18,69.85) v1(170.18,68.58) v1(171.45,71.12) v1(171.45,69.85) v1(171.45,68.58) v1(172.72,71.12) v1(172.72,69.85) v1(172.72,68.58) v1(173.99,71.12) v1(173.99,69.85) v1(173.99,68.58)
PFC-FB: length 15.3
  BOTTOM w0.508: R43.1 215.9,106.68 215.26,106.04 215.26,98.42 J3.23
PFC-VO: length 6.3
  BOTTOM w0.508: 214,97.16 210.95,100.2 R45.1
PFC_G_A: length 81.4
  ART03 w0.508: v1(192.28,96.39) 194.59,98.7 194.59,104.54 176.2,122.94 v1(166.5,122.94)
  ART05 w0.762: v1(150.24,118.75) 154.43,122.94 v1(166.5,122.94) 168.91,122.94 v1(173.48,118.36)
  BOTTOM w0.508: v1(166.5,122.94) C613.1 C499.1
  BOTTOM w0.762: v1(150.24,118.75) R34.1 154.7,119.65 C498.2 ; R35.1 v1(173.48,118.36)
PFC_G_B: length 49
  ART05 w0.762: v1(101.6,117.35) 103,118.75 v1(107.31,118.75) 113.28,118.75 117.98,123.44 123.06,123.44 v1(123.57,122.94) 127,119.51 129.41,119.51 v1(130.56,118.36)
  BOTTOM w0.762: C614.1 v1(123.57,122.94) ; R60.1 v1(130.56,118.36) ; C42.2 108.81,114.56 R75.2 106.3,114.58 R234.2 103.94,114.48 C45.1 101.72,114.43 ZD14.2 v1(101.6,117.35) ; R56.1 v1(107.31,118.75)
PFC_OCP: length 15.5
  ART05 w0.508: v1(216.53,100.33) 215.26,99.05 215.26,88.27 J3.15
  BOTTOM w0.508: R248.1 v1(216.53,100.33)
PFCDRVA: length 11.5
  BOTTOM w0.508: 159.66,119.53 U104.6 ; 159.66,119.53 159.66,119.35 160.15,118.87 163.45,118.87 163.7,119.13 R28.1 ; 159.66,119.53 159,118.87 157.36,118.87 R27.1
PFCDRVB: length 11.6
  BOTTOM w0.508: R51.1 114.43,118.87 116.33,118.87 116.74,119.28 ; 116.74,119.28 U106.6 ; 116.74,119.28 117.27,118.75 120.65,118.75 121.03,119.13 R52.1
PFCDRVC: length 17.8
  BOTTOM w0.508: U5.15 83.82,117.09 84.31,116.6 95.24,116.6 96.52,117.88 R29.1
PFCDRVD: length 6.6
  ART05 w0.508: v1(74.6,121.15) 76.2,121.15 v1(77.47,119.89)
  BOTTOM w0.381: U5.10 v1(77.47,119.89)
  BOTTOM w0.508: R48.1 v1(74.6,121.15)
PFCREF1.6V: length 15.2
  BOTTOM w0.508: U55.2 202.88,175.58 202.37,176.09 198.82,176.09 198,175.26 R538.2 198.12,174.5 R540.2 C478.1 196.73,172.84 195.32,174.25 C592.1 193.8,174.25 193.55,173.99 U2.3
PREF1.6V: length 8
  BOTTOM w0.508: U9.2 204.63,40.76 C93.1 202.69,40.76 202.31,41.15 R128.2 R126.2 199.33,41.15 198.82,40.64 U4.3
PWM1A: length 85.3
  ART05 w0.508: v1(161.8,109.47) 162.69,108.58 v1(169.42,108.58) 178.94,99.06 178.94,89.09 198.39,69.64 206.24,69.64 209.18,72.59 209.18,76.49 213.33,80.64 214.66,80.64 215.93,81.92 J3.11
  BOTTOM w0.508: R71.1 v1(161.8,109.47)
PWM1B: length 123.2
  ART05 w0.508: v1(118.87,109.47) 119.13,109.47 124.46,104.14 124.46,97.16 132.08,89.53 146.22,89.53 160.8,74.96 187.99,74.96 195.93,67.02 207.23,67.02 213.23,73.02 215.26,73.02 J3.5
  BOTTOM w0.381: R74.1 v1(118.87,109.47)
PWM1C: length 162.3
  ART05 w0.508: v1(84.45,107.31) 88.06,110.92 98.63,110.92 101.22,108.33 114.94,108.33 116.97,110.36 120.14,110.36 126.36,104.14 126.36,97.79 133.35,90.81 147.12,90.81 161.45,76.48 188.24,76.48 196.89,67.82 206.8,67.82 211.47,72.49 211.47,73.54 213.49,75.57 215.27,75.57 J3.7
  BOTTOM w0.508: R251.1 v1(84.45,107.31)
PWM1D: length 165.6
  ART05 w0.508: v1(83.19,107.31) 87.63,111.76 98.93,111.76 101.6,109.09 114.55,109.09 116.71,111.25 121.16,111.25 127.53,104.88 127.53,98.26 133.75,92.04 147.94,92.04 162.08,77.9 188.53,77.9 197.67,68.75 206.58,68.75 210.47,72.65 210.47,75.09 213.49,78.11 215.26,78.11 J3.9
  BOTTOM w0.508: R250.1 v1(83.19,107.31)
RLYCTRL1: length 160.9
  ART05 w0.508: 214,94.61 213.97,94.61 212.49,96.1 212.49,99.08 215.77,102.36 215.77,165.99 207.56,174.21 180.76,174.21 179.56,175.4 176.88,175.4 171.49,170.01 144.07,170.01 v1(138.53,164.47)
  BOTTOM w0.508: R5.2 v1(138.53,164.47)
SPGND: length 62
  TOP w1.016: C63.2 64.36,30.9 ; C63.2 62.23,33.03 ; C63.2 62.23,28.76 ; C63.2 60.1,30.9 ; C66.2 78.33,30.9 ; C66.2 76.2,33.03 ; C66.2 76.2,28.76 ; C66.2 74.07,30.9
  ART02 w1.016: 43.71,31.69 C78.2 ; C78.2 46.35,29.05 ; C78.2 49,31.69 ; C72.2 30.58,31.69 ; C72.2 27.94,34.33 ; C72.2 27.94,29.05 ; C63.2 65.13,30.9 ; C63.2 59.33,30.9 ; C63.2 62.23,28 ; C63.2 62.23,33.79 ; C66.2 79.1,30.9 ; C66.2 76.2,28 ; C66.2 73.3,30.9 ; C66.2 76.2,33.79
  BOTTOM w0.508: R107.2 30.39,31.25 29.95,31.69 C72.2
  vias: v1(57.78,31.75) v1(57.78,30.48) v1(57.78,29.21) v1(57.78,27.94) v1(58.97,21.35) v1(58.97,20.08) v1(59.05,31.75) v1(59.05,30.48) v1(59.05,29.21) v1(59.05,27.94) v1(60.24,21.35) v1(60.24,20.08) v1(61.51,21.35) v1(61.51,20.08) v1(63.42,21.35) v1(63.42,20.08) v1(64.69,21.35) v1(64.69,20.08) v1(65.96,21.35) v1(65.96,20.08) v1(68.58,32.38) v1(68.58,31.11) v1(69.85,32.38) v1(69.85,31.11) v1(71.12,32.38) v1(71.12,31.11) v1(72.26,42.93)
SR-PWM-A: length 145.2
  TOP w0.381: v1(107.95,30.48) 105.94,30.48 R141.2
  ART05 w0.381: v1(107.95,30.48) 115.83,22.6 115.83,18.28 123.24,10.87 200.14,10.87 205.49,16.22 205.49,19.2 213.36,27.07 213.36,30.2 215.1,31.94 216.72,31.94 218.36,33.59 218.36,37.32 217.03,38.66 215.86,38.66 214.66,37.47 214,37.47
SR-PWM-A-S: length 68.5
  TOP w0.508: R142.2 v1(87.63,29.72)
  ART05 w0.508: v1(87.63,29.72) 82.99,29.72 78.78,25.51 56.69,25.51 53.38,28.83 34.92,28.83 29.49,34.26 v1(26.85,34.26)
  BOTTOM w0.508: R559.1 26.85,35.39 v1(26.85,34.26)
SR-PWM-B: length 139.2
  TOP w0.381: R143.2 105.95,31.75 v1(107.95,31.75)
  ART05 w0.381: J5.10 217.73,36.27 217.73,33.9 216.74,32.91 215.06,32.91 212.67,30.53 212.67,27.61 204.59,19.52 204.59,16.52 199.57,11.51 124.45,11.51 118,17.96 118,21.7 v1(107.95,31.75)
SR-PWM-B-S: length 46.6
  TOP w0.508: R144.2 v1(87.63,30.99)
  ART05 w0.508: v1(87.63,30.99) 82.26,30.99 77.85,26.58 57.2,26.58 53.81,29.97 52.63,29.97 v1(48.06,34.54)
  BOTTOM w0.508: R557.1 v1(48.06,34.54)
SR-PWM-C: length 132.7
  TOP w0.381: R145.2 107.94,33.03 v1(108.84,32.14)
  ART05 w0.381: 214,34.92 214,32.88 211.99,30.87 211.99,28.22 203.45,19.69 203.45,16.63 198.96,12.14 125.45,12.14 119.73,17.86 119.73,21.24 109.46,31.51 109.46,31.51 v1(108.84,32.14)
SR-PWM-C-S: length 23
  TOP w0.508: R146.2 v1(87.63,32.26)
  ART05 w0.508: v1(87.63,32.26) 79.1,32.26 77.96,33.4 68.6,33.4 v1(67.74,34.26)
  BOTTOM w0.508: R562.1 67.74,35.39 v1(67.74,34.26)
SR-PWM-D: length 134.3
  TOP w0.508: v1(109.75,32.28) 107.75,34.28 R147.2
  ART05 w0.381: J5.12 215.34,36.12 213.5,36.12 212.71,35.33 212.71,32.58 211.23,31.1 211.23,28.75 200.93,18.45 182.53,18.45 176.86,12.78 126.43,12.78 121.83,17.37 121.83,20.24 110.33,31.74 110.29,31.74 v1(109.75,32.28)
SR-PWM-D-S: length 3.7
  TOP w0.508: R148.2 v1(87.63,33.53)
  ART05 w0.508: v1(88.97,34.54) 88.97,34.48 88.01,33.53 v1(87.63,33.53)
  BOTTOM w0.508: R561.1 v1(88.97,34.54)
SR_DETA_PRI: length 197.5
  ART03 w0.508: v1(93.55,56.86) 98.55,51.86 98.55,25.27 100.12,23.71 118.85,23.71 130.24,12.32 175.56,12.32 184.58,21.34 202.15,21.34 211.61,30.79 211.61,37.05 210.84,37.82 210.84,44.47 214,47.62
  BOTTOM w0.381: R568.2 86.36,61.59 85.41,62.54 D62.2 86.34,65.35 90.17,65.35 90.49,65.03 D61.2
  BOTTOM w0.508: v1(93.55,56.86) 90.92,56.86 87.5,60.29 R568.2
SR_DETB_PRI: length 193.5
  ART03 w0.508: 214,45.09 212.72,43.81 212.72,29.8 202.21,19.29 184,19.29 175.9,11.18 129.75,11.18 118.23,22.69 99.37,22.69 97.54,24.53 97.54,51.35 92.32,56.56 v1(92.32,57.89)
  BOTTOM w0.381: D61.1 92.39,62.54 91.44,61.59 R568.1 90.3,62.84 89.64,63.5 88.23,63.5 D62.1
  BOTTOM w0.508: v1(92.32,57.89) 90.3,59.91 R568.1
SR_L_G: length 106.9
  ART05 w0.508: v1(37.85,44.2) 41.28,40.77 53.34,40.77 56.26,37.85 63.63,37.85 65.02,39.24 73.79,39.24 v1(78.75,44.2) 82.18,40.77 93.73,40.77 98.61,35.88 98.61,29.03 107.2,20.43 110.47,20.43 111.45,19.45 111.45,17.54 109.79,15.88 U24.6
  BOTTOM w0.508: R543.1 41.53,45.09 C575.1 40.64,44.2 C573.2 v1(37.85,44.2) ; v1(78.75,44.2) C587.2 81.55,44.2 C589.1 82.43,45.09 R544.2
SRA_G: length 97.3
  ART02 w0.508: U22.6 83.88,17.53 56.13,17.53 53.06,20.6 26.54,20.6 23.11,24.03 23.11,39.5 24,40.39 24,42.55 22.1,44.45 v1(20.45,44.45)
  BOTTOM w0.508: v1(20.45,44.45) C567.2 C566.1 22.86,44.96 24.74,46.84 Q8.3
SRC_G: length 83.1
  ART02 w0.508: Q9.3 65.63,53.19 68.58,56.13 91.57,56.13 96.9,50.8 96.9,22.38 99.06,20.22 99.06,17.34 U23.6
  BOTTOM w0.508: v1(61.34,44.45) C581.2 C580.1 63.75,44.96 65.63,46.84 Q9.3
VDCLOW+15V: length 58
  ART03 w0.508: v1(123.9,39.5) 124.66,40.26 135.51,40.26 138.28,37.49 162.84,37.49 v1(164.85,39.5)
  ART05 w0.508: U21.7 169.48,34.87 v1(164.85,39.5)
  BOTTOM w0.381: R590.2 v1(123.9,39.5)
  BOTTOM w0.508: R588.2 164.79,39.56 v1(164.85,39.5)
VLOW+15V: length 186.3
  ART02 w0.508: v1(113.03,115.44) 113.03,121.14 v1(113.43,121.54)
  ART05 w0.508: U15.7 204.09,79.19 204.09,100.28 190.83,113.54 163.45,113.54 161.52,115.47 113.05,115.47 v1(113.03,115.44) 113.01,115.47 76.46,115.47 v1(74.93,113.94)
  BOTTOM w0.508: v1(74.93,113.94) R577.2 73.56,113.94 72.7,113.08 72.7,112.2 71.12,110.62 R66.1 C34.1 ; R234.1 106.3,111.78 R75.1 108.81,111.76 C42.1 112.14,111.76 113.03,112.65 v1(113.03,115.44) ; R581.2 v1(113.43,121.54)
VO1+: length 185.9
  ART05 w0.508: 216.53,23.5 215.26,22.23 212.74,22.23 209.88,19.36 209.88,12.4 206.76,9.28 151.52,9.28 143.19,0.95 83.5,0.95 82.38,2.07 82.38,6.52 80.64,8.26 59.69,8.26 v1(53.98,2.54)
  BOTTOM w0.508: v1(53.98,2.54) 54.11,2.41 R570.2
VO2+: length 76
  ART05 w0.508: 214,18.41 211.46,15.88 211.46,11.43 208.28,8.26 180.97,8.26 175.26,2.54 152.4,2.54 v1(149.99,4.95)
  BOTTOM w0.508: R118.2 v1(149.99,4.95)
VO+: length 13.1
  BOTTOM w0.508: C55.1 29.95,5.77 30.77,4.95 R84.1 ; C58.1 46.35,6.99 49.66,10.29 R571.1
  vias: v1(66.67,6.35) v1(67.94,6.35) v1(69.22,6.35) v1(70.48,6.35) v1(71.75,6.35) v1(73.03,6.35) v1(74.3,6.35) v1(75.56,6.35) v1(76.83,6.35) v1(78.11,6.35)
VP+5V: length 629.9
  TOP w0.508: R545.1 111.88,31.11 112.52,31.75 115.57,31.75 116.46,32.64 v1(116.46,35.06)
  ART03 w0.381: v1(204.34,39.62) 207.01,36.96 207.01,36.83
  ART03 w0.508: 207.01,36.83 207.01,30.48 201.81,25.28 v1(198.88,25.28) ; v1(200.03,43.81) 200.15,43.81 v1(204.34,39.62)
  ART03 w1.016: v1(116.46,35.06) 119.01,32.51 128.52,32.51 132.21,36.2 141.22,36.2 144.53,32.89 152.02,32.89 153.21,34.08 160.07,34.08 v1(161.67,35.69) 173.79,35.69 v1(176.46,33.02) 180.86,37.42 182.77,37.42 187.06,41.72 187.09,41.72 189.23,43.86 189.24,43.86 191.33,45.95 191.33,47.94 191.41,47.94 v1(192.2,48.73) 193.26,48.73 206.68,62.15 206.68,72.14 206.51,72.31 206.51,84.59 214,92.08
  GND04 w0.508: v1(198.88,25.28) 205.13,25.28 209.3,21.11 209.3,15.14 C594.1 ; v1(178.67,174.61) 178.67,171.85 v1(180.97,169.54)
  ART05 w0.508: v1(170.31,112.14) 169.93,112.52 162.31,112.52 161.16,113.67 129.29,113.67 v1(127.76,112.14) 125.55,114.35 77.3,114.35 74.66,111.71 74.66,108.99 73.03,107.36 v1(73.03,107.31) ; v1(178.67,174.61) 173.23,169.17 144.6,169.17 140.95,165.52 140.95,155.51 130.74,145.3 128.7,145.3 124.46,141.06 v1(124.46,137.28) ; v1(174.75,115.44) 193.17,115.44 207.65,100.97 207.65,95.89 211.46,92.08 214,92.08
  BOTTOM w0.381: v1(73.03,107.31) 72.65,107.69 C598.1 R575.1
  BOTTOM w0.508: v1(176.46,33.02) 179.7,33.02 C603.2 184.15,29.84 184.15,30.35 184.91,31.11 R582.2 ; v1(176.46,33.02) C608.1 ; v1(176.46,33.02) 175.49,33.02 R587.1 ; v1(178.67,174.61) 177.29,175.99 C595.2 R572.1 ; R134.2 v1(198.88,25.28) ; R126.1 v1(200.03,43.81) 195.11,48.73 v1(192.2,48.73) 192.2,47 R583.2 192.17,46.34 C604.2 ; R597.2 v1(124.46,137.28) ; C602.1 R579.1 v1(127.76,112.14) ; v1(174.75,115.44) 174.75,114.43 173.74,113.41 C601.1 R578.1 v1(170.31,112.14) ; C607.1 R586.1 v1(161.67,35.69) ; 198.12,170.77 197.71,170.36 186.38,170.36 184.3,168.28 C597.2 R574.1 v1(180.97,169.54) ; 198.12,170.77 198.51,170.38 201.88,170.38 204.29,172.79 209.81,172.79 217.81,164.8 217.81,93.98 217.17,93.34 215.26,93.34 214,92.08 ; 198.12,170.77 R540.1 ; R585.1 C606.1 119.12,31.12 117.85,32.39 116.7,32.39 C605.1 115.44,35.04 R584.1 v1(116.46,35.06)
VP+15V: length 391.1
  ART03 w1.016: v1(179.2,19.18) 179.2,28.32 181.04,30.16 185.81,30.16 188.54,32.89 188.54,37.43 190.59,39.47 190.6,39.47 v1(210.82,59.69) 211.05,59.92 211.05,81.51 214,84.45
  ART05 w0.508: v1(140.08,15.88) 143.26,19.05 155.57,19.05 v1(158.75,15.88) ; v1(211.46,94.61) 211.46,100.58 214.76,103.89 214.76,165.23 207.21,172.78 197.39,172.78 196.06,171.45 189.87,171.45 188.51,172.81 179.05,172.81 174.49,168.25 145.43,168.25 142.24,165.06 v1(142.24,152.4) 139.24,152.4 131.3,144.45 129.51,144.45 126.86,141.8 126.86,137.33 126.84,137.33 125.46,135.95 110.26,135.95 108.6,134.29 101.75,134.29 100.22,135.83 61.53,135.83 v1(59.05,133.35)
  BOTTOM w0.508: C1.1 143.5,154.17 R3.2 v1(142.24,152.4) ; v1(59.05,133.35) 58.29,132.58 C156.1 55.8,132.58 55.24,133.14 C158.1 53.58,133.86 R183.2 ; v1(211.46,94.61) 211.46,87 214,84.45 ; C173.1 139.2,18.42 C170.1 138.55,16.12 R184.2 v1(140.08,15.88)
VP+15V_DCDCA: length 39.6
  ART05 w0.508: v1(103.27,44.45) 104.41,43.31 108.08,43.31 111.12,40.26 116.71,40.26 119.13,37.85 119.13,31.62 122.3,28.45 127.44,28.45 U19.7
  BOTTOM w0.508: R591.2 v1(103.27,44.45)
VP+15V_DCDCB: length 17.1
  ART05 w0.508: v1(144.11,44.45) 144.11,34.76 U20.7
  BOTTOM w0.508: R589.2 v1(144.11,44.45)
VP+15V_HF_PFC: length 47.7
  ART03 w0.508: v1(191.77,99.06) 191.77,101.96 176.19,117.54 160.35,117.54 v1(156.35,121.54)
  BOTTOM w0.508: R580.2 v1(156.35,121.54)
VP-5V: length 102.7
  ART03 w0.508: J3.19 218.64,89.97 218.64,64.34 208.78,54.48 208.78,37.85 v1(209.8,36.83) 209.8,31.04 202.87,24.1 197.64,24.1 v1(196.98,24.77) 193.42,28.32 v1(184.78,28.32)
  BOTTOM w0.381: v1(184.78,28.32) 185.04,28.57 185.04,29.46 185.42,29.84 R122.2
  BOTTOM w0.508: U3.4 196.22,26.67 195.7,26.16 C88.1 v1(196.98,24.77)
VPFC: length 274.6
  TOP w1.016: C12.1 152.1,139.76 ; C12.1 154.94,136.66 ; C12.1 158.02,139.76 ; C9.1 169.93,139.76 ; C9.1 173.35,136.58 ; C9.1 176.94,139.76 ; C18.1 194.52,139.89 ; C18.1 188.38,139.89 ; C18.1 191.52,136.69
  ART02 w1.016: 183.95,43.97 CB6.1 ; CB6.1 186.34,46.35 ; CB6.1 183.95,48.74 ; CB6.1 181.56,46.35 ; 204.19,168.39 C16.1 206.9,165.21 ; D2.1 55.81,128.89 ; D2.1 53.27,131.42 ; D2.1 53.27,126.17 ; D2.1 50.79,128.89 ; C18.1 191.52,142.66 ; C18.1 188.96,139.89 ; C18.1 191.52,137.26 ; C18.1 194.17,139.89 ; C10.1 151.98,158.43 ; C10.1 154.53,161.35 ; C10.1 157.63,158.43 ; C10.1 154.53,155.36 ; C11.1 173.1,155.44 ; C11.1 175.79,158.3 ; C11.1 173.1,161.16 ; C11.1 170.42,158.3 ; C14.1 206.9,147 ; C14.1 206.9,152.63 ; C14.1 203.95,149.97 ; C9.1 173.35,142.42 ; C9.1 176.11,139.76 ; C9.1 170.64,139.76 ; C17.1 206.9,128.8 ; C17.1 204.24,131.56 ; C17.1 206.9,134.14 ; C15.1 191.52,161.01 ; C15.1 188.74,158.3 ; C15.1 191.52,155.56 ; C15.1 194.46,158.3 ; 154.94,142.7 C12.1 158,139.76 ; C13.1 206.9,110.35 ; C13.1 206.9,115.81 ; C13.1 204.35,113.14 ; CB7.1 185.06,33.66 ; CB7.1 179.86,33.66 ; CB7.1 182.43,36.12
  ART03 w1.016: C9.1 170.57,139.76 ; C9.1 173.35,142.39 ; C9.1 173.35,137.01 ; C9.1 176.09,139.76 ; C15.1 191.52,161.13 ; C15.1 188.82,158.3 ; C15.1 194.59,158.3 ; C15.1 191.52,155.49 ; C12.1 154.94,136.97 ; C12.1 157.74,139.76 ; C12.1 154.94,142.47 ; C12.1 153.23,139.76 152.47,140.52 ; 206.9,147.03 C14.1 204.06,149.97 ; C16.1 204.31,168.39 ; C16.1 206.9,171.12 ; C16.1 209.84,168.39 ; C16.1 206.9,165.6 ; C11.1 173.1,155.47 ; C11.1 173.1,160.97 ; C11.1 176.08,158.3 ; C11.1 170.4,158.3 ; C13.1 206.9,110.31 ; C13.1 204.18,113.14 ; C13.1 206.9,115.81 ; C18.1 191.52,136.95 ; C18.1 188.7,139.89 ; C18.1 191.52,142.62 ; C18.1 194.41,139.89 ; C10.1 151.77,158.43 ; C10.1 154.53,155.51 ; C10.1 157.43,158.43 ; C10.1 154.53,161.29 ; C17.1 204.34,131.56 ; C17.1 206.9,128.73 ; C17.1 206.9,134.29
  BOTTOM w0.508: C13.1 204.96,113.14 203.84,112.01 R38.2
  BOTTOM w1.016: C18.1 193.36,139.89 ; C18.1 191.52,141.67 ; C18.1 189.54,139.89 ; C18.1 191.52,137.91 ; C12.1 154.94,141.93 ; C12.1 154.94,137.68 ; C12.1 156.91,139.76 ; C12.1 153.05,139.76 ; C9.1 171.46,139.76 ; C9.1 173.35,141.67 ; C9.1 175.23,139.76 ; C9.1 173.35,137.79
VPFC_LF+15V: length 16.5
  TOP w0.508: 77.49,134.77 77.49,130.74 83.13,125.09 v1(83.82,125.09)
  BOTTOM w0.508: C599.2 86.12,123.55 R576.2 84.45,124.46 v1(83.82,125.09)
VS+5V: length 239.4
  TOP w0.508: R139.2 87.12,28.45 C100.1 v1(85.72,28.57) 85.72,29.26 85.68,29.3 85.68,32.94 v1(82.8,35.81)
  ART03 w0.508: J4.7 216.62,18.41 218.19,16.84 218.19,10.25 216.11,8.17 182.42,8.17 181.15,6.89 181.15,4.08 177.99,0.92 130.4,0.92 v1(129.16,2.16)
  ART05 w0.508: v1(127.64,9.27) 125.98,7.62 120.65,7.62 118.04,10.23 107.85,10.23 101.71,16.38 101.71,18.62 91.75,28.57 v1(85.72,28.57) ; v1(94.36,34.49) 93.03,35.81 v1(82.8,35.81) 80.9,35.81 80.15,35.06 v1(72.01,35.06) 71.9,35.18 53.13,35.18 v1(52.44,34.49) 50.67,36.26 32.31,36.26 v1(31.12,35.06)
  BOTTOM w0.508: R598.1 v1(31.12,35.06) ; R601.1 v1(94.36,34.49) ; R599.1 v1(52.44,34.49) ; R600.1 v1(72.01,35.06)
VS+15V: length 102.8
  ART03 w0.508: v1(122.68,8.51) 130.18,8.51 131.32,9.65 134.32,9.65 J8.4 137.92,6.05 140.77,6.05 145.06,1.75 177.02,1.75 180.03,4.76 180.03,7.2 181.95,9.12 214.86,9.12 J4.1
  vias: v1(95.5,4.83) v1(95.5,3.68) v1(95.5,2.54) v1(107.57,4.83) v1(107.57,3.68) v1(107.57,2.54) v1(119.51,3.05) v1(119.51,1.78)
VS+15V_DCDCA: length 103.7
  ART02 w0.508: U22.7 87.75,16.19 87.75,12.55 86.67,11.47 82.55,11.47 79.39,14.63 54.85,14.63 51.75,17.72 24.87,17.72 19.65,22.94 19.66,22.95 19.66,42.71 v1(17.92,44.45)
  BOTTOM w0.508: R592.2 v1(17.92,44.45)
VS+15V_DCDCB: length 81.5
  ART02 w0.508: U23.7 97.59,20.22 95.95,21.87 95.95,50.35 91.19,55.1 74.07,55.1 72.49,53.52 72.49,47.98 71.82,47.31 70.68,47.31 68.07,44.7 63.75,44.7 62.61,43.56 59.71,43.56 v1(58.82,44.45)
  BOTTOM w0.508: R594.2 v1(58.82,44.45)
VSLOW+15V: length 86.7
  ART05 w0.508: U24.7 106.55,18.41 97.09,27.88 97.09,35.37 92.96,39.5 v1(82.03,39.5) 79.11,36.58 55.59,36.58 52.58,39.58 41.24,39.58 v1(41.15,39.5)
  BOTTOM w0.508: v1(41.15,39.5) 41.13,39.51 R593.2 ; R595.2 v1(82.03,39.5)
N10486979: length 7.3
  BOTTOM w0.762: R34.2 150.11,121.78 R31.1 C6.2 150.62,125.1 150.62,128.62 Q2.3
N10631533: length 7.3
  BOTTOM w0.762: Q2.4 148.08,128.62 148.08,125.09 C6.1 R31.2 148.59,123.19 148.59,121.78 R602.2
N16148248: length 2.6
  BOTTOM w0.508: R89.1 35.93,7.75 R84.2
N16148380: length 9.4
  BOTTOM w0.508: C58.2 42.99,16.64 R93.2 R96.1
N16148534: length 2.7
  BOTTOM w0.508: R93.1 40.9,13.47 R90.2
N16148538: length 2.7
  BOTTOM w0.508: R89.2 38.36,10.29 R90.1
N16148540: length 2.7
  BOTTOM w0.508: R96.2 39.11,22.36 R101.1
N16148544: length 2.7
  BOTTOM w0.508: R102.2 34.03,28.07 R107.1
N16320789: length 2.6
  BOTTOM w0.508: R101.2 36.46,25.53 R102.1
N16587331: length 7.5
  BOTTOM w0.762: R35.2 173.38,121.5 R32.1 173.31,123.07 C7.2 173.85,125.16 173.85,128.59 Q3.3
N16587391: length 7.5
  BOTTOM w0.762: Q3.4 171.31,128.59 171.31,125.09 C7.1 171.79,123.07 R32.2 171.86,121.55 R604.2
N16589757: length 7.5
  BOTTOM w0.762: Q7.3 130.92,125.16 C25.2 130.38,123.07 R55.1 130.45,121.5 R60.2
N16589837: length 7.5
  BOTTOM w0.762: R603.2 128.93,121.55 R55.2 128.86,123.07 C25.1 128.38,125.09 Q7.4
N16589901: length 7.3
  BOTTOM w0.762: R56.2 107.19,121.78 R53.1 C23.2 107.7,125.1 Q6.3
N16589961: length 7.3
  BOTTOM w0.762: R605.2 105.66,121.78 105.66,123.19 R53.2 C23.1 105.16,125.09 Q6.4
N16599678: length 3.1
  BOTTOM w0.508: D48.2 93.96,118.75 94.36,119.14 94.36,120.65
N16600162: length 2.4
  BOTTOM w0.508: 70.9,120.62 70.9,119.78 70.5,119.38 D47.2
N16674941: length 7.9
  BOTTOM w0.508: R541.2 126.95,45.54 127.64,46.23 129.79,46.23 131.24,47.68 Q14.3
N16677707: length 8.2
  BOTTOM w0.508: R542.1 167.84,45.72 168.34,46.23 171.06,46.23 172.13,47.29 Q15.3
N16765027: length 3.1
  TOP w0.508: U10.1 104.42,29.21 R140.1 104.43,27.86 C102.2
N16765075: length 4.5
  TOP w0.381: R140.2 107.63,29.21 107.75,29.33 C101.1
  TOP w0.508: C101.1 110.24,29.33 R545.2
N16767690: length 4.2
  TOP w0.508: C103.2 R139.1 91.44,28.45 92.2,29.21 U10.16
N16833658: length 1.7
  TOP w0.508: U10.2 104.41,30.48 R141.1
N16833676: length 1.8
  TOP w0.508: U10.3 104.41,31.75 R143.1
N16833742: length 1.8
  TOP w0.508: R145.1 104.41,33.02 U10.4
N16833760: length 1.8
  TOP w0.508: U10.5 104.42,34.29 R147.1
N16833940: length 2.9
  TOP w0.508: U10.15 92.2,30.48 91.44,29.72 R142.1
N16833942: length 2.9
  TOP w0.508: R144.1 91.31,30.99 92.08,31.75 U10.14
N16834016: length 2.9
  TOP w0.508: R146.1 91.44,32.26 92.2,33.02 U10.13
N16834018: length 2.9
  TOP w0.508: U10.12 92.08,34.29 91.31,33.53 R148.1
N17093919: length 2.5
  BOTTOM w0.508: R3.1 R2.2
N17093922: length 2.5
  BOTTOM w0.508: R2.1 R1.2
N17244938: length 2.3
  BOTTOM w0.508: R15.2 R16.1
N17244999: length 2.3
  BOTTOM w0.508: R14.2 R15.1
N17245029: length 2.3
  BOTTOM w0.508: R20.2 R21.1
N17245032: length 2.3
  BOTTOM w0.508: R21.2 R22.1
N17252696: length 4
  BOTTOM w0.381: U103.2 C30.1
  BOTTOM w0.508: R62.1 C30.1
N17252758: length 4
  BOTTOM w0.508: U103.1 C29.2 R573.2
N17252921: length 4
  BOTTOM w0.381: U103.8 177.22,170.81 177.25,170.79
  BOTTOM w0.508: R574.2 C27.2 177.28,170.81 177.25,170.79
N17253061: length 2.8
  BOTTOM w0.381: U103.7 R63.2
N17253066: length 2.8
  BOTTOM w0.381: U103.6 R64.2
N17253305: length 6.9
  BOTTOM w0.508: R63.1 180.09,172.09 180.85,172.84 C28.2 R537.1 186.21,172.84 U2.5
N17253318: length 7
  BOTTOM w0.508: R64.1 180.72,174.25 R65.2 C31.1 184.15,174.25 185.05,174.25 185.31,173.99 U2.6
N17253751: length 8.2
  BOTTOM w0.508: U2.8 185.96,176.53 185.33,177.16 C26.2 184.27,177.93 183.77,178.44 180.85,178.44 180.46,178.05 R572.2
N17259772: length 2.3
  BOTTOM w0.508: R37.2 210.44,121.15 R30.1
N17259775: length 2.3
  BOTTOM w0.508: R39.2 213.24,116.59 R37.1
N17259778: length 2.2
  BOTTOM w0.508: R39.1 216.03,114.56 R43.2
N17259967: length 2.3
  BOTTOM w0.508: R40.2 204.47,106.55 R38.1
N17259969: length 3.5
  BOTTOM w0.508: R40.1 208.41,105.16 208.91,104.65 R45.2
N17264035: length 5.2
  BOTTOM w0.508: R543.2 44.18,45.2 45.93,46.95 Q12.3
N17264090: length 5.2
  BOTTOM w0.508: R544.1 85.08,45.2 86.83,46.95 Q13.3
N17266948: length 67.7
  ART03 w0.508: v1(138.43,2.54) 132.08,2.54 128.27,6.35 118.87,6.35 114.97,10.25 80.56,10.25 v1(79.88,10.93)
  BOTTOM w0.508: R114.2 v1(79.88,10.93) ; R115.1 139.06,3.17 v1(138.43,2.54)
N17266951: length 2.3
  BOTTOM w0.508: R118.1 R115.2
N17268549: length 7.2
  BOTTOM w0.508: U3.5 190.06,26.67 189.94,26.55 C83.2 188.7,26.55 188.19,26.04 R117.1 C82.2 R116.2
N17268684: length 13.1
  BOTTOM w0.508: 192.68,29.21 192.79,29.11 192.79,25.78 191.77,24.77 R116.1 ; 192.68,29.21 193.36,29.89 D8.1 ; 192.68,29.21 U3.7
N17268693: length 6.9
  BOTTOM w0.508: U3.6 190.39,27.94 190.26,28.06 C83.1 188.95,28.06 188.19,27.3 R123.1 C87.2 R122.1
N17268930: length 4.3
  BOTTOM w0.508: R582.1 187.57,31.24 C248.2 190.02,31.24 190.78,30.48 U3.8
N17268988: length 10.2
  BOTTOM w0.508: R127.2 C92.1 R129.2 201.11,25.4 200.98,25.52 200.98,26.5 200.69,26.79 R134.1 C97.2 199.32,28.45 198.81,27.94 U3.3
N17269030: length 6.4
  BOTTOM w0.508: R138.1 C99.2 201.11,30.48 200.6,29.97 C97.1 199.34,29.97 198.58,29.21 U3.2
N17269076: length 17.7
  ART03 w0.508: v1(198.75,30.48) 204.41,30.48 v1(204.43,30.5)
  BOTTOM w0.508: v1(198.75,30.48) U3.1 197.13,30.4 195.88,30.4 195.26,31.03 D8.2 ; v1(204.43,30.5) 204.45,30.48 204.55,30.48 205.36,29.67 205.36,28.77 204.53,27.94 R127.1
N17269867: length 3.8
  BOTTOM w0.508: C89.1 186.54,37.59 185.93,38.2 R121.2 R120.1
N17269877: length 7.3
  BOTTOM w0.508: U4.5 190.06,39.37 189.94,39.25 C91.1 188.27,39.25 188.15,39.37 R121.1 187.45,38.74 187.96,38.23 C90.1 R119.2
N17270011: length 8.9
  BOTTOM w0.508: U4.6 190.06,40.64 189.94,40.76 C91.2 188.27,40.76 188.15,40.64 R130.1 C96.1 187.45,42.58 R132.1 188.25,44.01 C94.1
N17270029: length 1.7
  BOTTOM w0.508: R135.1 R130.2
N17270191: length 5.3
  BOTTOM w0.508: U4.8 192.63,43.18 193.29,43.84 193.29,44.89 C84.2 193.59,45.19 193.59,45.4 194.03,45.84 R583.1
N17272262: length 6.5
  BOTTOM w0.381: U9.1 206.69,41.63 206.47,41.85 204.4,41.85 203.83,42.42 R136.2
  BOTTOM w0.508: R136.2 202.26,42.42 202.01,42.67 R128.1
N17288635: length 5.7
  BOTTOM w0.508: U5.1 85.09,111.25 84.45,110.62 R251.2 C35.1 R67.1
